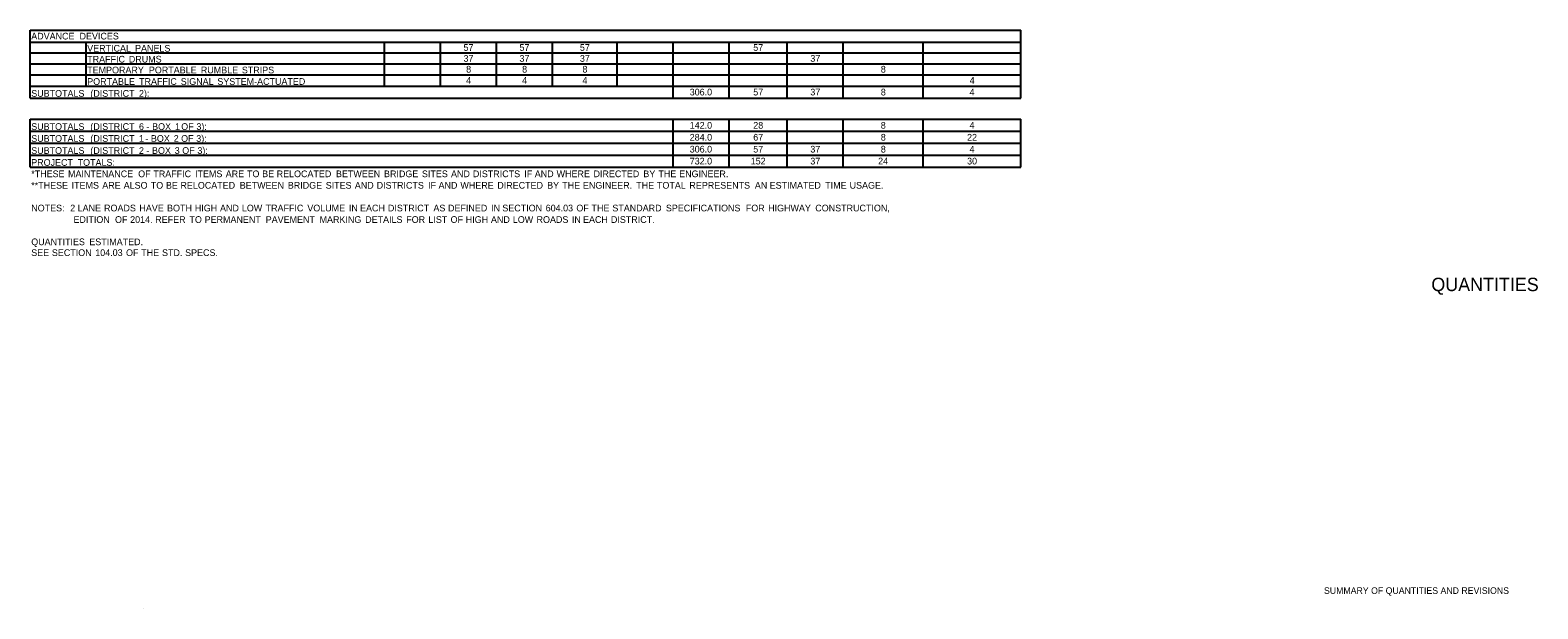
# Model space of a CAD drawing. Extents: x 542596 to 1930787, y -1948294 to 596640.
# Drawn here: x 544436 to 545789, y -1947326 to -1946807 of the extents above; entities that cross this region are included whole.
import ezdxf

# ---------------------------------------------------------------- set-up
doc = ezdxf.new("R2010")
doc.units = 0
for name, color, linetype in [('Default', 7, 'Continuous'), ('R_Border', 7, 'Continuous'), ('R_Border Prem', 7, 'Continuous')]:
    doc.layers.add(name, color=color, linetype=linetype)

msp = doc.modelspace()

# ---------------------------------------------------------------- linework, layer by layer
at = {"layer": 'Default'}
for p, q in [((544436.4, -1946806.8), (545325.1, -1946806.8)), ((544436.4, -1946867.8), (544436.4, -1946806.8)), ((544436.4, -1946867.8), (544436.4, -1946806.8)), ((544486.6, -1946806.8), (545237.4, -1946806.8)), ((545237.4, -1946806.8), (545325.1, -1946806.8)), ((545325.1, -1946867.8), (545325.1, -1946806.8)), ((545325.1, -1946867.8), (545325.1, -1946806.8)), ((544436.4, -1946817.6), (545325.1, -1946817.6)), ((544486.6, -1946857.1), (544486.6, -1946817.6)), ((544486.6, -1946857.1), (544486.6, -1946817.6)), ((544754.3, -1946857.1), (544754.3, -1946817.6)), ((544754.3, -1946857.1), (544754.3, -1946817.6)), ((544804.5, -1946857.1), (544804.5, -1946817.6)), ((544804.5, -1946857.1), (544804.5, -1946817.6)), ((544854.7, -1946857.1), (544854.7, -1946817.6)), ((544854.7, -1946857.1), (544854.7, -1946817.6)), ((544904.9, -1946857.1), (544904.9, -1946817.6)), ((544904.9, -1946857.1), (544904.9, -1946817.6)), ((544962.9, -1946857.1), (544962.9, -1946817.6)), ((545013.1, -1946857.1), (545013.1, -1946817.6)), ((545013.1, -1946867.8), (545013.1, -1946817.6)), ((545063.4, -1946867.8), (545063.4, -1946817.6)), ((545063.4, -1946867.8), (545063.4, -1946817.6)), ((545115.5, -1946867.8), (545115.5, -1946817.6)), ((545115.5, -1946867.8), (545115.5, -1946817.6)), ((545165.7, -1946867.8), (545165.7, -1946817.6)), ((545165.7, -1946867.8), (545165.7, -1946817.6)), ((545237.4, -1946867.8), (545237.4, -1946817.6)), ((544436.4, -1946827.3), (545325.1, -1946827.3)), ((544436.4, -1946837.1), (545325.1, -1946837.1)), ((544436.4, -1946846.8), (545325.1, -1946846.8)), ((544436.4, -1946857.1), (544754.3, -1946857.1)), ((544436.4, -1946857.1), (545325.1, -1946857.1)), ((544754.3, -1946857.1), (545013.1, -1946857.1)), ((545237.4, -1946867.8), (545237.4, -1946857.1)), ((544436.4, -1946867.8), (545325.1, -1946867.8)), ((544436.4, -1946886.8), (545325.1, -1946886.8)), ((544436.4, -1946886.8), (545325.1, -1946886.8)), ((544436.4, -1946929.7), (544436.4, -1946886.8)), ((544436.4, -1946929.7), (544436.4, -1946886.8)), ((545013.1, -1946929.7), (545013.1, -1946886.8)), ((545063.4, -1946929.7), (545063.4, -1946886.8)), ((545115.5, -1946929.7), (545115.5, -1946886.8)), ((545165.7, -1946929.7), (545165.7, -1946886.8)), ((545237.4, -1946929.7), (545237.4, -1946886.8)), ((545325.1, -1946929.7), (545325.1, -1946886.8)), ((544436.4, -1946897.5), (545325.1, -1946897.5)), ((545013.1, -1946929.7), (545013.1, -1946897.5)), ((544436.4, -1946908.2), (545325.1, -1946908.2)), ((544436.4, -1946919), (545325.1, -1946919)), ((544436.4, -1946929.7), (545325.1, -1946929.7)), ((544538.1, -1947325.8), (544538.1, -1947325.8))]:
    msp.add_line(p, q, dxfattribs=at)

# ---------------------------------------------------------------- texts
for s, p in [('ADVANCE', (544437.4, -1946815.2)), (' DEVICES', (544478.5, -1946815.2)), ('VERTICAL', (544487.6, -1946826.1)), (' PANELS', (544528.3, -1946826.1)), ('57', (544825.1, -1946825.4)), ('57', (544875.3, -1946825.4)), ('57', (544929.5, -1946825.4)), ('57', (545085, -1946825.4)), ('TRAFFIC', (544487.6, -1946835.9)), ('TEMPORARY', (544487.6, -1946845.6)), (' DRUMS', (544522.7, -1946835.9)), (' PORTABLE', (544540.7, -1946845.6)), (' RUMBLE', (544587.3, -1946845.6)), (' STRIPS', (544624.1, -1946845.6)), ('37', (544825.1, -1946835.2)), ('8', (544827.5, -1946844.9)), ('37', (544875.3, -1946835.2)), ('8', (544877.7, -1946844.9)), ('37', (544929.5, -1946835.2)), ('8', (544931.8, -1946844.9)), ('37', (545136.2, -1946835.2)), ('8', (545199.4, -1946844.9)), ('PORTABLE', (544487.6, -1946855.9)), (' TRAFFIC', (544531.9, -1946855.9)), (' SIGNAL', (544569.3, -1946855.9)), (' SYSTEM-ACTUATED', (544602.1, -1946855.9)), ('4', (544827.5, -1946854.9)), ('4', (544877.7, -1946854.9)), ('4', (544931.8, -1946854.9)), ('4', (545279.1, -1946854.9)), ('SUBTOTALS', (544437.4, -1946866.6)), (' (DISTRICT', (544488.2, -1946866.6)), (' 2):', (544531.8, -1946866.6)), ('306.0', (545028, -1946865.4)), ('57', (545085, -1946865.4)), ('37', (545136.2, -1946865.4)), ('8', (545199.4, -1946865.4)), ('4', (545279, -1946865.4)), ('SUBTOTALS', (544437.4, -1946896.3)), (' (DISTRICT', (544488.2, -1946896.3)), (' 6', (544531.8, -1946896.3)), (' -', (544538.5, -1946896.3)), (' BOX', (544543.6, -1946896.3)), (' 1', (544564.1, -1946896.3)), (' OF', (544569.7, -1946896.3)), (' 3):', (544583.3, -1946896.3)), ('142.0', (545028, -1946895.2)), ('28', (545085, -1946895.2)), ('8', (545199.4, -1946895.2)), ('4', (545279, -1946895.2)), ('SUBTOTALS', (544437.4, -1946907)), (' (DISTRICT', (544488.2, -1946907)), (' 1', (544531.8, -1946907)), (' -', (544537.5, -1946907)), (' BOX', (544542.5, -1946907)), (' 2', (544563, -1946907)), (' OF', (544569.6, -1946907)), (' 3):', (544583.2, -1946907)), ('284.0', (545028, -1946905.9)), ('67', (545085, -1946905.9)), ('8', (545199.4, -1946905.9)), ('22', (545276.8, -1946905.9)), ('SUBTOTALS', (544437.4, -1946917.8)), (' (DISTRICT', (544488.2, -1946917.8)), (' 2', (544531.8, -1946917.8)), (' -', (544538.4, -1946917.8)), (' BOX', (544543.5, -1946917.8)), (' 3', (544563.9, -1946917.8)), (' OF', (544570.6, -1946917.8)), (' 3):', (544584.2, -1946917.8)), ('306.0', (545028, -1946916.6)), ('57', (545085, -1946916.6)), ('37', (545136.2, -1946916.6)), ('8', (545199.4, -1946916.6)), ('4', (545279, -1946916.6)), ('*THESE', (544437.4, -1946938.7)), ('PROJECT', (544437.4, -1946928.5)), (' MAINTENANCE', (544468.2, -1946938.7)), (' TOTALS:', (544476.8, -1946928.5)), (' OF', (544531.1, -1946938.7)), (' TRAFFIC', (544544.7, -1946938.7)), (' ITEMS', (544582.1, -1946938.7)), (' ARE', (544609.6, -1946938.7)), (' TO', (544628.7, -1946938.7)), (' BE', (544642.3, -1946938.7)), (' RELOCATED', (544655.3, -1946938.7)), (' BETWEEN', (544708.5, -1946938.7)), (' BRIDGE', (544751.6, -1946938.7)), (' SITES', (544785.6, -1946938.7)), (' AND', (544811.7, -1946938.7)), (' DISTRICTS', (544831.3, -1946938.7)), (' IF', (544877.4, -1946938.7)), (' AND', (544886.8, -1946938.7)), (' WHERE', (544906.4, -1946938.7)), (' DIRECTED', (544939.5, -1946938.7)), (' BY', (544984.2, -1946938.7)), (' THE', (544997.7, -1946938.7)), (' ENGINEER.', (545016.3, -1946938.7)), ('732.0', (545028, -1946927.3)), ('152', (545082.7, -1946927.3)), ('37', (545136.2, -1946927.3)), ('24', (545197, -1946927.3)), ('30', (545276.8, -1946927.3)), ('**THESE', (544437.4, -1946949)), (' ITEMS', (544471.4, -1946949)), (' ARE', (544498.9, -1946949)), (' ALSO', (544518.1, -1946949)), (' TO', (544542.4, -1946949)), (' BE', (544556, -1946949)), (' RELOCATED', (544569, -1946949)), (' BETWEEN', (544622.2, -1946949)), (' BRIDGE', (544665.3, -1946949)), (' SITES', (544699.3, -1946949)), (' AND', (544725.4, -1946949)), (' DISTRICTS', (544745, -1946949)), (' IF', (544791.1, -1946949)), (' AND', (544800.5, -1946949)), (' WHERE', (544820.1, -1946949)), (' DIRECTED', (544853.2, -1946949)), (' BY', (544897.9, -1946949)), (' THE', (544911.4, -1946949)), (' ENGINEER.', (544930, -1946949)), (' THE', (544977.8, -1946949)), (' TOTAL', (544996.4, -1946949)), (' REPRESENTS', (545025.5, -1946949)), (' AN', (545084.2, -1946949)), (' ESTIMATED', (545097.5, -1946949)), (' TIME', (545147.3, -1946949)), (' USAGE.', (545169.2, -1946949)), ('NOTES:', (544437.4, -1946969.4)), ('  2', (544467.9, -1946969.4)), ('                 EDITION', (544437.4, -1946979.7)), (' LANE', (544476.8, -1946969.4)), (' ROADS', (544500.5, -1946969.4)), (' OF', (544510.3, -1946979.7)), (' 2014.', (544523.9, -1946979.7)), (' HAVE', (544532.2, -1946969.4)), (' REFER', (544546.4, -1946979.7)), (' BOTH', (544557, -1946969.4)), (' TO', (544577.1, -1946979.7)), (' HIGH', (544581.9, -1946969.4)), (' PERMANENT', (544590.7, -1946979.7)), (' AND', (544604.5, -1946969.4)), (' LOW', (544624.1, -1946969.4)), (' TRAFFIC', (544645.4, -1946969.4)), (' PAVEMENT', (544645.5, -1946979.7)), (' VOLUME', (544682.8, -1946969.4)), (' MARKING', (544693.8, -1946979.7)), (' IN', (544720.1, -1946969.4)), (' EACH', (544730.1, -1946969.4)), (' DETAILS', (544734.7, -1946979.7)), (' DISTRICT', (544755.1, -1946969.4)), (' FOR', (544771.5, -1946979.7)), (' LIST', (544791.4, -1946979.7)), (' AS', (544795.9, -1946969.4)), (' DEFINED', (544809, -1946969.4)), (' OF', (544811.3, -1946979.7)), (' HIGH', (544824.9, -1946979.7)), (' AND', (544847.5, -1946979.7)), (' IN', (544847.6, -1946969.4)), (' SECTION', (544857.7, -1946969.4)), (' LOW', (544867.1, -1946979.7)), (' ROADS', (544888.4, -1946979.7)), (' 604.03', (544896.6, -1946969.4)), (' IN', (544920.1, -1946979.7)), (' OF', (544924.1, -1946969.4)), (' EACH', (544930.1, -1946979.7)), (' THE', (544937.7, -1946969.4)), (' DISTRICT.', (544955.1, -1946979.7)), (' STANDARD', (544956.4, -1946969.4)), (' SPECIFICATIONS', (545004.4, -1946969.4)), (' FOR', (545076.1, -1946969.4)), (' HIGHWAY', (545096.1, -1946969.4)), (' CONSTRUCTION,', (545138.4, -1946969.4)), ('QUANTITIES', (544437.4, -1946999.7)), (' ESTIMATED.', (544487.3, -1946999.7)), ('SEE', (544437.4, -1947009.4)), (' SECTION', (544453.7, -1947009.4)), (' 104.03', (544492.6, -1947009.4)), (' OF', (544520.2, -1947009.4)), (' THE', (544533.8, -1947009.4)), (' STD.', (544552.5, -1947009.4)), (' SPECS.', (544573.2, -1947009.4))]:
    msp.add_text(s, height=6, dxfattribs=at).set_placement(p)
at = {"layer": 'R_Border'}
msp.add_text('QUANTITIES', height=12, rotation=360, dxfattribs=at).set_placement((545693.2, -1947040.9))
at = {"layer": 'R_Border Prem'}
msp.add_text('SUMMARY OF QUANTITIES AND REVISIONS', height=5.862, rotation=360, dxfattribs=at).set_placement((545596.9, -1947312.4))

doc.saveas('drawing.dxf')
